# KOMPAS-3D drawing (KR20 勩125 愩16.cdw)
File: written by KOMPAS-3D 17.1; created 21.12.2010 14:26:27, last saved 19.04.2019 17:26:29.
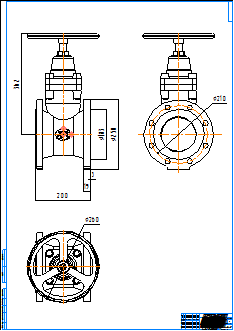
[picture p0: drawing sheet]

Title block, sheet 1: name: KR20 Ду125 Ру16; material: Внимание! Данный продукт является объектом авторского права ООО «Торговый Дом АДЛ». / Запрещается изменение, копирование, распространение / (в том числе путем копирования на другие сайты и ресурсы в Интернете) / или любое иное использование информации и объектов без предварительного / согласия правообладателя (ООО «Торговый Дом АДЛ»).; scale: 1:1; sheets: 1; organisation: ООО "Торговый дом АДЛ"; sheet format: A0; stored path: \\adlc.lan\data\АДЛ_ПКД\3D-модели\ADL production\Клиновые задвижки серии KR ГРАНАР\Клиновые задвижки KR20\KOMPAS 2D\KR20 Ду125 Ру16.cdw

Views: Спереди 1, Проекционный вид 2, Проекционный вид 3
Dimensions and other numbers on the sheet: 3; 19; 200; 183; 250; 210; 362; 260; 1:1; 1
